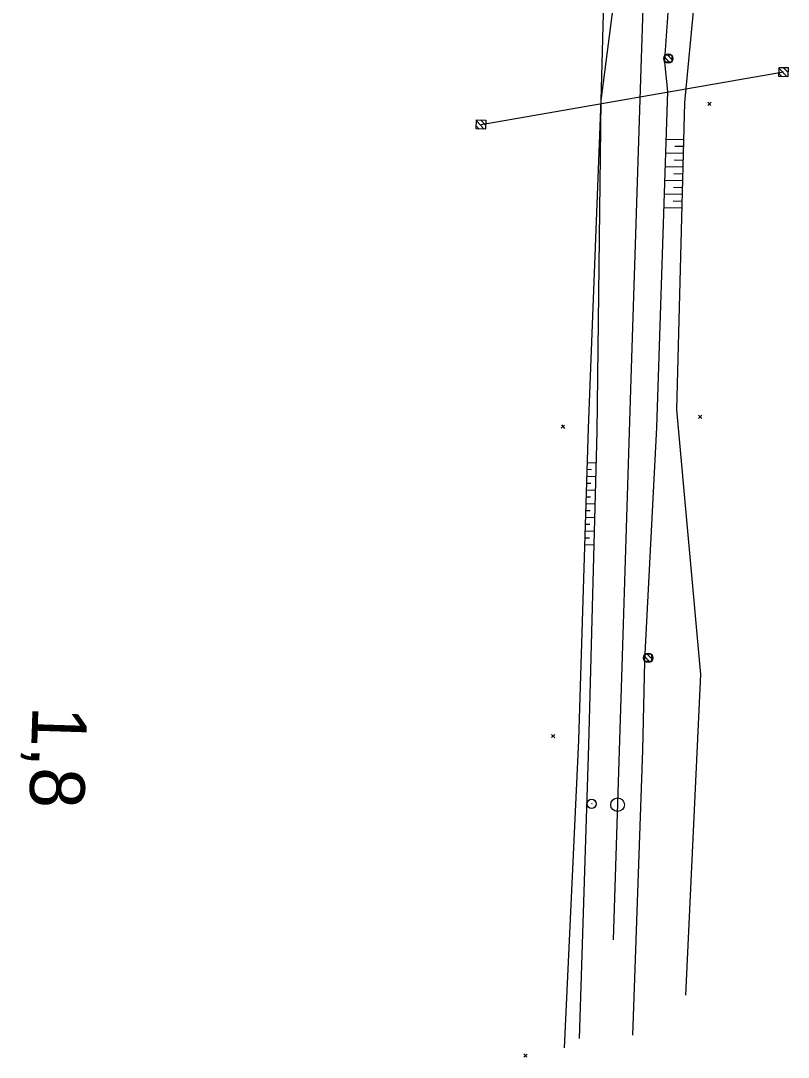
# Model space of a CAD drawing. Extents: x -738085 to -734426, y -1122197 to -1119748.
# Drawn here: x -735543.9 to -735459.8, y -1120714.2 to -1120600.6 of the extents above; entities that cross this region are included whole.
import ezdxf

# ---------------------------------------------------------------- set-up
doc = ezdxf.new("R2010")
doc.units = 0
for name, color, linetype in [('Vrstva 1', 7, 'Continuous'), ('Vrstva 11', 7, 'Continuous'), ('Vrstva 12', 7, 'Continuous'), ('Vrstva 25', 7, 'Continuous'), ('Vrstva 36', 7, 'Continuous'), ('Vrstva 48', 7, 'Continuous'), ('Vrstva 49', 7, 'Continuous'), ('Vrstva 7', 7, 'Continuous')]:
    doc.layers.add(name, color=color, linetype=linetype)

msp = doc.modelspace()

# ---------------------------------------------------------------- linework, layer by layer
at = {"layer": 'Vrstva 1'}
for points in [[(-735475.33, -1120587.19), (-735475.9, -1120604.74)], [(-735475.33, -1120587.19), (-735475.9, -1120604.74)], [(-735475.9, -1120604.74), (-735477.02, -1120639.86), (-735477.98, -1120670.26), (-735478.96, -1120701.34)], [(-735475.9, -1120604.74), (-735477.02, -1120639.86), (-735477.98, -1120670.26), (-735478.96, -1120701.34)]]:
    msp.add_lwpolyline(points, dxfattribs=at)
at = {"layer": 'Vrstva 11'}
for p, q in [((-735473.39, -1120604.56), (-735472.75, -1120605.23)), ((-735473.11, -1120604.31), (-735472.48, -1120604.97)), ((-735475.58, -1120670.21), (-735474.95, -1120670.89)), ((-735475.31, -1120669.96), (-735474.68, -1120670.62))]:
    msp.add_line(p, q, dxfattribs=at)
for centre in [(-735472.94, -1120604.77), (-735475.14, -1120670.43)]:
    msp.add_circle(centre, 0.5, dxfattribs=at)
at = {"layer": 'Vrstva 12'}
msp.add_line((-735474.75, -1120670.84), (-735474.72, -1120670.04), dxfattribs=at)
for points in [[(-735473.35, -1120605.16), (-735473.33, -1120604.36), (-735472.53, -1120604.39), (-735472.55, -1120605.19), (-735473.35, -1120605.16)], [(-735475.55, -1120670.81), (-735475.52, -1120670.01), (-735474.72, -1120670.04), (-735474.75, -1120670.84), (-735475.55, -1120670.81)], [(-735475.55, -1120670.81), (-735474.75, -1120670.84), (-735474.75, -1120670.84)], [(-735475.52, -1120670.01), (-735474.72, -1120670.04), (-735474.72, -1120670.04)]]:
    msp.add_lwpolyline(points, dxfattribs=at)
at = {"layer": 'Vrstva 25'}
msp.add_line((-735493.45, -1120612.01), (-735460.3, -1120606.25), dxfattribs=at)
at = {"layer": 'Vrstva 36'}
for p, q in [((-735460.79, -1120605.85), (-735459.93, -1120606.76)), ((-735460.34, -1120605.75), (-735459.81, -1120606.32)), ((-735460.81, -1120606.42), (-735460.5, -1120606.75)), ((-735493.94, -1120611.61), (-735493.09, -1120612.52)), ((-735493.49, -1120611.51), (-735492.96, -1120612.07)), ((-735493.96, -1120612.17), (-735493.65, -1120612.5))]:
    msp.add_line(p, q, dxfattribs=at)
for points in [[(-735459.79, -1120605.77), (-735459.82, -1120606.77), (-735460.82, -1120606.74), (-735460.79, -1120605.74), (-735459.79, -1120605.77)], [(-735492.94, -1120611.53), (-735492.97, -1120612.52), (-735493.97, -1120612.49), (-735493.94, -1120611.49), (-735492.94, -1120611.53)]]:
    msp.add_lwpolyline(points, dxfattribs=at)
at = {"layer": 'Vrstva 48'}
for p, q in [((-735471.22, -1120613.68), (-735473.2, -1120613.63)), ((-735471.26, -1120615.18), (-735473.25, -1120615.13)), ((-735471.24, -1120614.43), (-735472.23, -1120614.41)), ((-735471.28, -1120615.93), (-735472.28, -1120615.91)), ((-735471.3, -1120616.68), (-735473.3, -1120616.63)), ((-735471.32, -1120617.43), (-735472.32, -1120617.41)), ((-735471.34, -1120618.18), (-735473.35, -1120618.13)), ((-735471.38, -1120619.68), (-735473.39, -1120619.63)), ((-735471.36, -1120618.93), (-735472.37, -1120618.91)), ((-735471.4, -1120620.43), (-735472.41, -1120620.4)), ((-735471.42, -1120621.18), (-735473.44, -1120621.13)), ((-735481.85, -1120649.03), (-735480.84, -1120649.06)), ((-735481.89, -1120650.53), (-735480.88, -1120650.56)), ((-735481.87, -1120649.78), (-735481.36, -1120649.79)), ((-735481.92, -1120651.28), (-735481.41, -1120651.29)), ((-735481.96, -1120652.78), (-735481.45, -1120652.79)), ((-735481.94, -1120652.03), (-735480.92, -1120652.06)), ((-735481.98, -1120653.53), (-735480.96, -1120653.56)), ((-735482.03, -1120655.03), (-735481, -1120655.06)), ((-735482.01, -1120654.28), (-735481.5, -1120654.29)), ((-735482.05, -1120655.78), (-735481.54, -1120655.79)), ((-735482.1, -1120657.28), (-735481.58, -1120657.29)), ((-735482.08, -1120656.53), (-735481.05, -1120656.56)), ((-735482.12, -1120658.02), (-735481.09, -1120658.06))]:
    msp.add_line(p, q, dxfattribs=at)
at = {"layer": 'Vrstva 49'}
for p, q in [((-735471.12, -1120609.59), (-735469.04, -1120587.48)), ((-735478.02, -1120591.35), (-735480.33, -1120609.37)), ((-735480.33, -1120609.37), (-735481.73, -1120645.28)), ((-735471.99, -1120643.25), (-735471.12, -1120609.59)), ((-735468.25, -1120609.57), (-735468.61, -1120609.91)), ((-735468.6, -1120609.55), (-735468.26, -1120609.92)), ((-735469.37, -1120672.27), (-735471.99, -1120643.25)), ((-735484.3, -1120644.94), (-735484.66, -1120645.28)), ((-735484.65, -1120644.92), (-735484.31, -1120645.29)), ((-735469.26, -1120643.85), (-735469.62, -1120644.2)), ((-735469.61, -1120643.84), (-735469.27, -1120644.21)), ((-735481.73, -1120645.28), (-735482.79, -1120679.46)), ((-735471.01, -1120707.38), (-735469.37, -1120672.27)), ((-735485.37, -1120678.83), (-735485.73, -1120679.17)), ((-735485.72, -1120678.82), (-735485.38, -1120679.18)), ((-735482.79, -1120679.46), (-735484.33, -1120713.16)), ((-735488.41, -1120713.84), (-735488.77, -1120714.18)), ((-735488.76, -1120713.83), (-735488.42, -1120714.19))]:
    msp.add_line(p, q, dxfattribs=at)
for points in [[(-735478.43, -1120538.86), (-735478.81, -1120534.12), (-735478.1, -1120531.49), (-735475.77, -1120532.1), (-735475.84, -1120533.13), (-735475.85, -1120533.39), (-735476.71, -1120533.65), (-735477.3, -1120534.59), (-735478.43, -1120538.86), (-735479.68, -1120561.4), (-735479.97, -1120595.79), (-735480.33, -1120609.37), (-735480.75, -1120645.68), (-735481.69, -1120680), (-735482.7, -1120712.12)], [(-735470.98, -1120552.47), (-735471.96, -1120585.42), (-735473.33, -1120604.36), (-735473.35, -1120605.16), (-735473.03, -1120608.37), (-735474.22, -1120645.2), (-735475.52, -1120670.01), (-735475.55, -1120670.81), (-735475.77, -1120680.56), (-735476.87, -1120711.77)]]:
    msp.add_lwpolyline(points, dxfattribs=at)
at = {"layer": 'Vrstva 7'}
msp.add_line((-735481.32, -1120686.38), (-735481.33, -1120686.48), dxfattribs=at)
for centre, radius in [((-735478.49, -1120686.52), 0.75), ((-735478.49, -1120686.52), 0.75), ((-735481.32, -1120686.43), 0.5)]:
    msp.add_circle(centre, radius, dxfattribs=at)

# ---------------------------------------------------------------- texts
msp.add_text('1,8', height=6, rotation=268.1993, dxfattribs=at).set_placement((-735542.59, -1120675.68))
msp.add_text('1,8', height=6, rotation=268.1993, dxfattribs=at).set_placement((-735542.59, -1120675.68))

doc.saveas('drawing.dxf')
